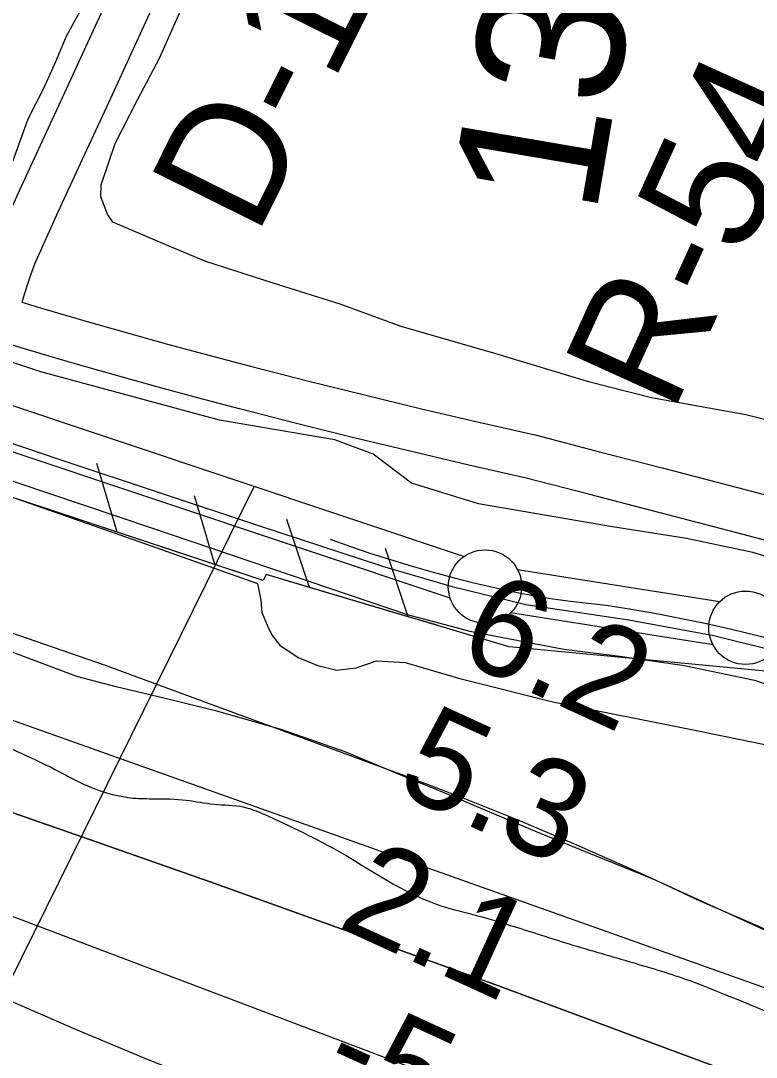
# Model space of a CAD drawing. Extents: x 3734862 to 3772949, y 391520 to 417239.
# Drawn here: x 3741720 to 3742221, y 407967 to 408673 of the extents above; entities that cross this region are included whole.
import ezdxf

# ---------------------------------------------------------------- set-up
doc = ezdxf.new("R2010")
doc.units = 0
for name, color, linetype in [('V-FLOD-BASE', 7, 'Continuous'), ('V-LEVE-TOET', 7, 'Continuous'), ('V-RIVR-EDGE', 7, 'Continuous'), ('V-RIVR-RANG', 7, 'Continuous'), ('V-RIVR-RANG-IDEN', 7, 'Continuous'), ('V-ROAD-CNTR', 7, 'Continuous'), ('V-RRAP-FSHR', 7, 'Continuous'), ('V-SITE-VEGE', 7, 'Continuous'), ('V-SURV-IDEN', 7, 'Continuous'), ('V-SURV-LINE', 7, 'Continuous'), ('V-TOPO-DPTH', 7, 'Continuous'), ('V-TOPO-MINR', 7, 'Continuous'), ('V-TOPO-WATR', 7, 'Continuous')]:
    doc.layers.add(name, color=color, linetype=linetype)

msp = doc.modelspace()

# ---------------------------------------------------------------- linework, layer by layer
at = {"layer": 'V-FLOD-BASE'}
msp.add_lwpolyline([(3741357.137, 408502.83400000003), (3741447.661, 408473.662), (3741558.435, 408435.67), (3741637.4250000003, 408410.916), (3741748.199, 408373.435), (3741882.3140000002, 408328.918), (3741966.682, 408301.315), (3742013.1040000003, 408287.751), (3742064.154, 408275.195), (3742134.474, 408264.605), (3742192.2090000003, 408254.074), (3742233.255, 408243.873), (3742303.0100000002, 408221.98600000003), (3742379.4250000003, 408196.218), (3742465.843, 408167.578), (3742525.589, 408147.021), (3742568.413, 408132.703), (3742689.193, 408092.609), (3742775.093, 408062.946), (3742799.1890000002, 408053.079), (3742852.9990000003, 408026.12700000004)], dxfattribs=at)
at = {"layer": 'V-LEVE-TOET'}
for points in [[(3742853.687, 408092.552), (3742773.204, 408127.843), (3742640.359, 408169.016), (3742476.767, 408225.74), (3742318.301, 408280.384), (3742218.792, 408310.623), (3742173.634, 408320.071), (3742123.335, 408328.00200000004), (3742031.98, 408343.821), (3741986.33, 408357.895), (3741960.222, 408377.531), (3741934.071, 408387.409), (3741855.5470000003, 408400.602), (3741733.963, 408433.507), (3741608.312, 408475.164), (3741420.097, 408539.188), (3741268.3030000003, 408592.77400000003)], [(3741157.722, 408544.851), (3741405.9390000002, 408460.52400000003), (3741600.835, 408397.49700000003), (3741810.0810000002, 408327.216), (3741983.424, 408268.395), (3742026.004, 408256.904), (3742090.153, 408244.802), (3742128.14, 408240.00800000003), (3742172.284, 408233.647), (3742220.007, 408223.67100000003), (3742324.631, 408188.788), (3742481.555, 408134.14900000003), (3742625.667, 408085.22000000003), (3742673.369, 408070.624), (3742762.594, 408038.376), (3742798.487, 408024.862), (3742869.1920000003, 407985.507)]]:
    msp.add_lwpolyline(points, dxfattribs=at)
at = {"layer": 'V-RIVR-EDGE'}
msp.add_spline([(3740900.5804832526, 408488.7607591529), (3740941.700981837, 408478.2594238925), (3740985.5366537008, 408468.65569270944), (3741012.202688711, 408464.06816566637), (3741026.2005238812, 408456.3468507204), (3741048.315927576, 408440.0144431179), (3741059.5974714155, 408430.9433678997), (3741079.4632746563, 408419.1381125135), (3741115.5910482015, 408400.96242050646), (3741134.5491848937, 408387.8029326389), (3741159.8363902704, 408374.1756358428), (3741187.834296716, 408359.637318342), (3741219.450570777, 408345.5422126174), (3741247.458539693, 408335.07330087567), (3741273.6657101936, 408327.7739547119), (3741324.259127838, 408308.2060164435), (3741367.6303449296, 408293.62968516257), (3741397.445820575, 408282.704145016), (3741437.1953158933, 408266.32813337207), (3741481.0086267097, 408247.6812782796), (3741515.791112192, 408234.0305023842), (3741546.0553898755, 408221.74737559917), (3741577.679490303, 408210.8173632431), (3741596.214540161, 408209.4150545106), (3741611.5923230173, 408211.18566551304), (3741627.866591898, 408209.7889470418), (3741654.51921028, 408199.77554565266), (3741683.8858838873, 408190.20759214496), (3741714.59896361, 408176.56687872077), (3741739.890641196, 408164.7482067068), (3741769.245016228, 408150.2065350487), (3741796.809773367, 408143.3559909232), (3741811.2776535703, 408142.86805705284), (3741832.9789148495, 408141.91007814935), (3741851.9627667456, 408139.1501827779), (3741871.853167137, 408137.29236369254), (3741889.019449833, 408130.9196909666), (3741941.855759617, 408104.11166330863), (3741978.426744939, 408082.31760368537), (3742006.4302416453, 408070.04006716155), (3742031.2820616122, 408063.1962313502), (3742056.132763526, 408055.90023934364), (3742093.6326583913, 408044.05137991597), (3742137.0083476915, 408031.2836734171), (3742175.8635930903, 408018.9793036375), (3742202.51509342, 408008.5137460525), (3742263.040294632, 407982.591023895), (3742313.1670213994, 407957.1461731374), (3742385.8803149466, 407923.0544520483), (3742430.1390736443, 407901.69354173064), (3742465.818045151, 407884.87543636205), (3742513.6962895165, 407864.40989401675), (3742632.029282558, 407810.7625332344), (3742679.00656869, 407791.6556955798), (3742732.3028610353, 407768.01164323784), (3742777.463696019, 407745.7441844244), (3742821.2848332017, 407730.2624227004), (3742862.3919151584, 407714.3352130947), (3742898.537577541, 407703.39402021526), (3742934.681003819, 407691.54851494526), (3742978.0555750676, 407678.32865225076), (3743028.200190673, 407660.11830062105), (3743075.641931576, 407645.98406306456), (3743127.6052344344, 407631.8386449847), (3743163.743070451, 407617.732358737), (3743235.1267286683, 407594.4957404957), (3743327.2916830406, 407563.97319271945), (3743354.8609123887, 407558.931273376), (3743372.940451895, 407556.1736141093), (3743388.7569743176, 407552.51723271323), (3743422.1841092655, 407539.32196717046), (3743470.5256903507, 407523.37686872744), (3743543.2837059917, 407507.37139545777), (3743582.5978159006, 407497.7788447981), (3743628.681970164, 407483.1958052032), (3743672.9563815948, 407468.16508162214), (3743714.522328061, 407454.9496911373), (3743752.478851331, 407444.9083384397), (3743782.3122158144, 407441.2172974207), (3743812.5921462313, 407435.2643573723), (3743846.038288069, 407429.75574715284), (3743877.2147045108, 407420.63547763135), (3743909.2808986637, 407405.63494146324), (3743934.1014131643, 407386.1307321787), (3743951.2453348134, 407370.7149355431), (3743984.2001886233, 407349.3819765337), (3744023.0464896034, 407333.4603571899), (3744065.9756129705, 407322.95454972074), (3744101.675827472, 407314.7274120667), (3744133.7587924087, 407306.50921883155), (3744170.3599651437, 407296.92337648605), (3744207.4121760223, 407286.884259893), (3744225.0339690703, 407281.86693770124), (3744312.23862192, 407256.7825628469), (3744386.801908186, 407239.4161487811), (3744416.179762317, 407234.36975722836), (3744442.3969952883, 407231.13981682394), (3744469.5274850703, 407231.5248898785), (3744498.9198738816, 407232.35652886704), (3744525.594853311, 407231.3862513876), (3744550.005697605, 407229.06509558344), (3744580.7321939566, 407220.850256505), (3744636.7637845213, 407206.2426197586), (3744682.3857201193, 407187.5912924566), (3744706.329873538, 407179.39322416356), (3744748.361392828, 407171.602589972), (3744781.8041805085, 407164.7375111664), (3744803.051049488, 407162.87633792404), (3744835.5772262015, 407151.03977707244), (3744852.283526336, 407141.50312903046), (3744920.944184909, 407114.20381334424), (3744972.8773003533, 407087.85017798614), (3745004.947966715, 407074.6582666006), (3745034.319112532, 407066.8989378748), (3745066.8575878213, 407060.0360951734), (3745090.817393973, 407058.1682136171), (3745113.40731491, 407050.8778118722), (3745145.9211930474, 407034.06753287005), (3745173.0181412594, 407020.8879200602), (3745183.3730116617, 407002.775957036), (3745197.806232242, 406988.2711811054), (3745221.284812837, 406974.64835651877), (3745251.1047606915, 406965.53144115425), (3745295.845862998, 406956.3776300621), (3745336.0832921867, 406954.46949862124), (3745373.6077842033, 406952.568075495), (3745407.9593564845, 406947.5093853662), (3745449.9897577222, 406939.26659497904), (3745482.9826253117, 406933.30694661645), (3745526.394092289, 406935.00823837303), (3745594.221993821, 406936.64915530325), (3745631.750958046, 406936.55635695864), (3745647.5876054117, 406941.03878708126), (3745660.719141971, 406948.6930188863), (3745673.8327896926, 406949.1127515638), (3745691.0091348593, 406946.80948459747), (3745714.498895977, 406937.7082219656), (3745744.7553472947, 406922.2600018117), (3745760.5428003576, 406906.8475593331), (3745773.1618058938, 406890.08647463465), (3745781.290554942, 406885.9969439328), (3745798.0080355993, 406880.98185784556), (3745819.7081788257, 406879.5717227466), (3745874.386654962, 406866.32390874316), (3745905.104206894, 406854.4918201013), (3745930.8379782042, 406838.6026242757), (3745969.2108799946, 406814.09115526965), (3745999.0162931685, 406799.0962093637), (3746028.82953271, 406787.2663568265), (3746069.4978750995, 406776.7661396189), (3746110.167335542, 406766.71807860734), (3746144.959883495, 406757.1367084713), (3746173.873282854, 406747.1177168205), (3746214.5427432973, 406737.0696558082), (3746271.4786462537, 406722.4597829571), (3746336.102322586, 406708.2830594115), (3746374.5031756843, 406695.07549529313), (3746423.295794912, 406678.67712260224), (3746514.1210514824, 406654.940271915), (3746563.3725352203, 406641.25371834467), (3746619.392945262, 406622.1245196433), (3746668.6388387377, 406606.1771850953), (3746708.3995145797, 406594.3227354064), (3746774.3651248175, 406574.26462716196), (3746826.3396081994, 406564.6407710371), (3746866.124881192, 406562.73375764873), (3746897.312478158, 406558.135050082), (3746931.657342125, 406550.36342278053)], degree=3, dxfattribs=at)
at = {"layer": 'V-RIVR-RANG'}
msp.add_line((3741879.0770999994, 408355.3277000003), (3741480.6760999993, 407548.31060000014), dxfattribs=at)
at = {"layer": 'V-ROAD-CNTR'}
for points in [[(3741692.6233325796, 408489.74363223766), (3741693.2772389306, 408492.045513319), (3741695.9630441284, 408500.7619267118), (3741698.840916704, 408509.41526300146), (3741702.05726126, 408518.41580500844), (3741718.5689345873, 408554.979109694), (3741735.02763571, 408590.9393727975), (3741751.641253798, 408626.75417248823), (3741802.5522428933, 408737.652365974), (3741853.1959602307, 408847.74888177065), (3741899.205737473, 408948.41802630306), (3741952.585300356, 409063.1242358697), (3742010.331281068, 409189.4127065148), (3742072.735830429, 409326.25786089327), (3742124.7849146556, 409442.0943332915), (3742189.1470783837, 409580.94240530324), (3742253.4802625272, 409720.53129551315), (3742308.771171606, 409840.09096228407), (3742388.711897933, 410014.5776341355), (3742473.8403317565, 410199.3201933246), (3742557.8918733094, 410384.89351832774), (3742657.291548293, 410602.167595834)], [(3741721.326470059, 408480.99995872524), (3741722.0447610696, 408483.528486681), (3741724.5349558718, 408491.6100732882), (3741727.2030832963, 408499.63273699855), (3741729.89873874, 408507.1761949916), (3741745.879065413, 408542.562890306), (3741762.2743642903, 408578.3846272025), (3741778.8807462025, 408614.1838275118), (3741829.811757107, 408725.1256340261), (3741880.46603977, 408835.2451182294), (3741926.448262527, 408935.85397369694), (3741979.8266996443, 409050.55776413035), (3742037.6207189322, 409176.9512934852), (3742100.066169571, 409313.88613910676), (3742152.0770853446, 409429.6376667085), (3742216.378921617, 409568.35559469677), (3742280.717737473, 409707.95670448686), (3742336.022828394, 409827.5470377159), (3742415.972102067, 410002.0523658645), (3742501.1276682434, 410186.85380667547), (3742585.196126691, 410372.4644816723), (3742684.566451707, 410589.674404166)], [(3741720.9785414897, 408481.10461789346), (3741735.9615099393, 408476.5976438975), (3741764.004915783, 408468.38012087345), (3741792.1059018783, 408460.3536876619), (3741820.2614836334, 408452.5256068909), (3741848.4705438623, 408444.8906561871), (3741876.72741377, 408437.4530646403), (3741915.4980881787, 408427.5546783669), (3741954.3370516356, 408417.90304680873), (3741993.2384627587, 408408.5048984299), (3742032.19885721, 408399.35810911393), (3742071.4887024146, 408390.403258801), (3742114.4159914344, 408379.23595177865), (3742157.126348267, 408368.1281190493), (3742199.8363931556, 408357.02136742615), (3742242.805178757, 408345.85236043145), (3742275.401147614, 408336.12797545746), (3742307.7226066, 408326.25512218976), (3742339.9798863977, 408316.1673254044), (3742372.1706110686, 408305.86400678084), (3742404.291386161, 408295.3493096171), (3742436.3423595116, 408284.6238626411), (3742468.100588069, 408273.7612237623), (3742478.935585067, 408270.34939480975)], [(3742234.7408212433, 408316.95163956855), (3742192.2876068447, 408327.9866325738), (3742149.5756517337, 408339.0938809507), (3742106.864008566, 408350.20204822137), (3742064.3772975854, 408361.254741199), (3742025.43714279, 408370.1298908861), (3741986.2875372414, 408379.32110157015), (3741947.1969483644, 408388.7649531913), (3741908.1699118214, 408398.4633216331), (3741869.19858623, 408408.41293535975), (3741840.7334561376, 408415.90534381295), (3741812.3245163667, 408423.5943931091), (3741783.9680981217, 408431.4783123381), (3741755.667084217, 408439.56187912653), (3741727.422490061, 408447.83835610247), (3741698.679473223, 408456.4844418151)], [(3741930.926, 408319.554), (3741944.819, 408314.639), (3741958.789, 408309.943), (3741972.832, 408305.466), (3741986.94, 408301.21), (3742001.117, 408297.178), (3742015.3540000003, 408293.367), (3742029.649, 408289.781), (3742044, 408286.42), (3742058.399, 408283.282)], [(3742058.399, 408283.282), (3742070.433, 408281.058), (3742082.512, 408279.096), (3742094.632, 408277.396), (3742106.787, 408275.963), (3742118.969, 408274.791), (3742136.119, 408271.994), (3742153.2260000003, 408268.95), (3742170.288, 408265.66500000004), (3742187.302, 408262.139), (3742204.2660000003, 408258.37200000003), (3742221.1720000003, 408254.365), (3742238.019, 408250.117)]]:
    msp.add_lwpolyline(points, dxfattribs=at)
at = {"layer": 'V-RRAP-FSHR'}
for p, q in [((3741786.059, 408324.37200000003), (3741772.077, 408371.159)), ((3741852.495, 408302.32300000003), (3741838.512, 408349.109)), ((3741916.958, 408286.803), (3741901.509, 408333.125)), ((3741984.055, 408266.857), (3741968.606, 408313.18))]:
    msp.add_line(p, q, dxfattribs=at)
for points in [[(3738902.293381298, 409472.05737969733), (3740332.6069263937, 408753.8471600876), (3741222.946255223, 408371.2807597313), (3742367.6717602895, 407964.03391135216)], [(3741885.294, 408291.43700000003), (3741623.779, 408378.232), (3741440.632, 408438.30700000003), (3741241.33, 408499.824), (3741053.031, 408559.014), (3740880.236, 408628.54600000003), (3740717.648, 408719.542), (3740545.6350000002, 408780.531), (3740315.4960000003, 408858.271), (3740127.6350000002, 408979.39), (3739988.6410000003, 409101.918), (3739872.917, 409177.10000000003), (3739715.1920000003, 409236.84500000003), (3739511.406, 409313.517), (3739328.592, 409381.064), (3739254.605, 409391.05700000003), (3739223.7120000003, 409392.859)], [(3741786.059, 408324.37200000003), (3741719.623, 408346.422)], [(3741852.495, 408302.32300000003), (3741786.058, 408324.373)], [(3741916.958, 408286.803), (3741887.461, 408295.571), (3741885.294, 408291.43700000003), (3741852.494, 408302.32300000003)], [(3744098.274, 407565.304), (3743827.379, 407635.72000000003), (3743592.332, 407695.86100000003), (3743255.415, 407779.58400000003), (3743049.168, 407872.952), (3742832.975, 408002.576), (3742229.916, 408229.48600000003), (3742052.933, 408246.38300000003), (3741887.461, 408295.571), (3741885.294, 408291.43700000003)], [(3741984.055, 408266.857), (3741916.957, 408286.803)], [(3742003.843, 408260.97500000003), (3741984.054, 408266.858)]]:
    msp.add_lwpolyline(points, dxfattribs=at)
at = {"layer": 'V-SITE-VEGE'}
for points in [[(3742308.894, 408380.407), (3742213.957, 408404.284), (3742149.918, 408415.827), (3742107.758, 408426.646), (3742043.127, 408446.00800000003), (3741979.43, 408464.428), (3741937.917, 408479.62200000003), (3741891.399, 408494.21400000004), (3741846.443, 408508.798), (3741820.2290000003, 408519.54600000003), (3741783.097, 408535.657), (3741779.369, 408540.988), (3741774.731, 408552.891), (3741775.083, 408561.018), (3741784.588, 408589.114), (3741800.044, 408619.371), (3741814.863, 408647.13), (3741836.029, 408695.496)], [(3741762.031, 408681.911), (3741751.156, 408661.953), (3741744.043, 408644.63300000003), (3741735.833, 408626.693), (3741725.112, 408605.637), (3741714.821, 408577.389), (3741707.255, 408563.668), (3741696.313, 408563.873), (3741687.568, 408565.788), (3741660.573, 408576.853), (3741649.809, 408581.434), (3741637.636, 408586.177), (3741615.943, 408594.093), (3741608.142, 408597.566), (3741598.779, 408601.204), (3741565.1920000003, 408605.887), (3741538.93, 408606.47500000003), (3741521.4420000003, 408610.618), (3741486.944, 408621.716), (3741465.096, 408629.632), (3741443.25, 408638.328), (3741420.7830000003, 408648.277), (3741386.6, 408659.842), (3741359.126, 408668.251)], [(3741267.1750000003, 408500.05100000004), (3741435.865, 408441.818), (3741624.3340000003, 408379.848), (3741801.34, 408317.754), (3741881.608, 408289.439), (3741883.8170000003, 408278.14400000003), (3741884.471, 408269.802), (3741888.4250000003, 408260.582), (3741891.52, 408253.969), (3741896.701, 408247.522), (3741909.166, 408239.132), (3741922.684, 408233.514), (3741935.519, 408230.503), (3741948.723, 408232.011), (3741962.463, 408236.80700000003), (3741982.078, 408235.679), (3742018.4960000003, 408224.922), (3742082.668, 408208.831), (3742180.341, 408189.291), (3742291.193, 408166.567), (3742428.9790000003, 408108.297), (3742590.3570000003, 408046.101), (3742710.724, 408015.172), (3742817.656, 407969.545)], [(3742259.89, 408039.427), (3742219.3370000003, 408057.496), (3742182.944, 408073.114), (3742153.037, 408087.174), (3742071.992, 408120.14900000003), (3742008.735, 408147), (3741976.494, 408159.995), (3741941.313, 408174.912), (3741897.6210000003, 408190.043), (3741853.7490000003, 408202.569), (3741818.537, 408211.23600000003), (3741785.235, 408219.026), (3741758.525, 408226.092), (3741701.494, 408247.532), (3741651.052, 408267.033), (3741611.884, 408283.012), (3741572.878, 408297.60000000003), (3741526.239, 408312.917), (3741454.1, 408334.945), (3741400.176, 408352.032), (3741354.915, 408365.43200000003)]]:
    msp.add_lwpolyline(points, dxfattribs=at)
at = {"layer": 'V-SURV-LINE'}
for points in [[(3740908.4490125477, 408680.0622699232), (3742022.2388270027, 408307.9302322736)], [(3742012.7490834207, 408279.4706980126), (3740898.9594024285, 408651.6026910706)], [(3742058.515962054, 408299.06509452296), (3742196.4269493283, 408277.2605802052)], [(3742191.752784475, 408247.62694555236), (3742053.842360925, 408269.4313707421)]]:
    msp.add_lwpolyline(points, dxfattribs=at)
for centre in [(3742036.447340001, 408287.36804), (3742213.82162, 408259.3235899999)]:
    msp.add_circle(centre, 25, dxfattribs=at)
at = {"layer": 'V-TOPO-DPTH'}
for points in [[(3741344.1757719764, 408256.8803595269), (3741361.763542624, 408250.8929114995), (3741379.3922432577, 408245.0237309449), (3741519.8005438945, 408199.0638355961), (3741602.4312121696, 408171.63878150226), (3741684.9068352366, 408143.76118395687), (3741767.1498904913, 408115.2047712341), (3741849.2379005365, 408086.19581505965), (3741944.277962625, 408052.16852125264), (3741978.705863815, 408039.76864273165), (3742013.1020652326, 408027.2819560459), (3742047.450716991, 408014.6650571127), (3742081.7676689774, 408001.96135001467), (3742154.060026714, 407975.0438151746), (3742224.5397753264, 407948.9264685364), (3742295.073380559, 407922.9561001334), (3742365.6877707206, 407897.20619908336), (3742436.3560175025, 407871.60327626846), (3742746.9182101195, 407759.6358470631), (3742769.2256532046, 407751.6652469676), (3742791.5628874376, 407743.77981111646), (3742813.9448083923, 407736.02212163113)], [(3742807.6368422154, 407616.30608748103), (3742777.9447145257, 407626.4862109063), (3742748.2722379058, 407636.7230311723), (3742718.629237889, 407647.0448966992), (3742689.005888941, 407657.4234590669), (3742584.292799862, 407694.278416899), (3742502.2553190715, 407722.91572695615), (3742420.121409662, 407751.27138134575), (3742337.8428573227, 407779.2045522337), (3742255.467876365, 407806.8560674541), (3742015.1876293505, 407886.8265702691), (3741986.610928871, 407896.57519909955), (3741958.136234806, 407906.6066211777), (3741929.814550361, 407917.06223312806), (3741901.594872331, 407927.8006383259), (3741856.928760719, 407945.18040704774), (3741806.66022129, 407965.3071471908), (3741756.6683046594, 407986.08164415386), (3741707.091322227, 408007.82777634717), (3741657.7909625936, 408030.22166536), (3741263.8529723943, 408213.82029983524)], [(3742807.6368422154, 407616.30608748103), (3742777.9447145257, 407626.4862109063), (3742748.2722379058, 407636.7230311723), (3742718.629237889, 407647.0448966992), (3742689.005888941, 407657.4234590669), (3742584.292799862, 407694.278416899), (3742502.2553190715, 407722.91572695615), (3742420.121409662, 407751.27138134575), (3742337.8428573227, 407779.2045522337), (3742255.467876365, 407806.8560674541), (3742015.1876293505, 407886.8265702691), (3741986.610928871, 407896.57519909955), (3741958.136234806, 407906.6066211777), (3741929.814550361, 407917.06223312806), (3741901.594872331, 407927.8006383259), (3741856.928760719, 407945.18040704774), (3741806.66022129, 407965.3071471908), (3741756.6683046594, 407986.08164415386), (3741707.091322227, 408007.82777634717), (3741657.7909625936, 408030.22166536), (3741263.8529723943, 408213.82029983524)]]:
    msp.add_lwpolyline(points, dxfattribs=at)
at = {"layer": 'V-TOPO-MINR'}
for points in [[(3742803.59199821, 407672.5649234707), (3742778.1067845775, 407681.03993041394), (3742772.8652696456, 407682.7983173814), (3742767.6300411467, 407684.5750683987), (3742762.404242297, 407686.37936549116), (3742757.1847298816, 407688.2020266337), (3741982.88, 407960.88), (3741639.5684787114, 408090.9699588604), (3741567.4514388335, 408119.09262547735), (3741495.715283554, 408148.13083503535), (3741424.550455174, 408178.54235900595), (3741353.7665113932, 408209.86942591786), (3741248.695523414, 408257.58388049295), (3741230.7895914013, 408265.8586564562), (3741212.959108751, 408274.2902911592), (3741195.241800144, 408282.9572139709), (3741177.5999408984, 408291.78099552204), (3741042.605867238, 408360.4206770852), (3740957.5210023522, 408403.6769169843), (3740872.432699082, 408446.92639126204), (3740787.3392382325, 408490.16571710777), (3740702.2423389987, 408533.39827733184), (3740440.9891087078, 408666.1055584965)], [(3742809.25, 407787.49), (3742137.5557717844, 408094.25004957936), (3742098.4485726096, 408111.5792981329), (3742059.096240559, 408128.31352971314), (3742019.376209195, 408144.15523583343), (3741979.411044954, 408159.40192498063), (3741778.0340889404, 408233.63395142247), (3741719.0995901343, 408254.0894898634), (3741659.7123465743, 408273.02557149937), (3741599.645985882, 408289.6824679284), (3741539.126880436, 408304.8199075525), (3741453.958710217, 408324.40333261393), (3741435.7359336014, 408328.80284139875), (3741417.5836769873, 408333.4650213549), (3741399.5372003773, 408338.5212080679), (3741381.56124377, 408343.8400659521), (3741363.7013661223, 408349.5387312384), (3741345.925580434, 408355.48060808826)], [(3742807.6368422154, 407616.30608748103), (3742777.9447145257, 407626.4862109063), (3742748.2722379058, 407636.7230311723), (3742718.629237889, 407647.0448966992), (3742689.005888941, 407657.4234590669), (3742584.292799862, 407694.278416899), (3742502.2553190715, 407722.91572695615), (3742420.121409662, 407751.27138134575), (3742337.8428573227, 407779.2045522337), (3742255.467876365, 407806.8560674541), (3742015.1876293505, 407886.8265702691), (3741986.610928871, 407896.57519909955), (3741958.136234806, 407906.6066211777), (3741929.814550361, 407917.06223312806), (3741901.594872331, 407927.8006383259), (3741856.928760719, 407945.18040704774), (3741806.66022129, 407965.3071471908), (3741756.6683046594, 407986.08164415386), (3741707.091322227, 408007.82777634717), (3741657.7909625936, 408030.22166536), (3741263.8529723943, 408213.82029983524)]]:
    msp.add_lwpolyline(points, dxfattribs=at)
at = {"layer": 'V-TOPO-WATR'}
msp.add_lwpolyline([(3742813.9448083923, 407736.02212163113), (3742791.5628874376, 407743.77981111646), (3742769.2256532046, 407751.6652469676), (3742746.9182101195, 407759.6358470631), (3742436.3560175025, 407871.60327626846), (3742365.6877707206, 407897.20619908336), (3742295.073380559, 407922.9561001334), (3742224.5397753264, 407948.9264685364), (3742154.060026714, 407975.0438151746), (3742081.7676689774, 408001.96135001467), (3742047.450716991, 408014.6650571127), (3742013.1020652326, 408027.2819560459), (3741978.705863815, 408039.76864273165), (3741944.277962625, 408052.16852125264), (3741849.2379005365, 408086.19581505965), (3741767.1498904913, 408115.2047712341), (3741684.9068352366, 408143.76118395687), (3741602.4312121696, 408171.63878150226), (3741519.8005438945, 408199.0638355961), (3741379.3922432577, 408245.0237309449), (3741361.763542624, 408250.8929114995), (3741344.1757719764, 408256.8803595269)], dxfattribs=at)

# ---------------------------------------------------------------- texts
at = {"layer": 'V-RIVR-RANG'}
for s, p in [('6.2', (3742015.4272727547, 408239.0805262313)), ('5.3', (3741974.028272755, 408148.0525262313)), ('2.1', (3741934.7887847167, 408056.0352059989)), ('-5', (3741922.649613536, 407951.60997618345))]:
    msp.add_text(s, height=67.00000000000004, rotation=335.3983257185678, dxfattribs=at).set_placement(p)
at = {"layer": 'V-RIVR-RANG-IDEN'}
for s, height, rotation, p in [('D-100', 83.00000000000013, 63.584325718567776, (3741880.6775922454, 408524.9578142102)), ('R-54.7', 82.99999799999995, 65.54442589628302, (3742163.8713151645, 408403.959215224))]:
    msp.add_text(s, height=height, rotation=rotation, dxfattribs=at).set_placement(p)
at = {"layer": 'V-SURV-IDEN'}
msp.add_text('1388+62.9', height=100, rotation=80.2897222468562, dxfattribs=at).set_placement((3742111.6254817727, 408538.526473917))

doc.saveas('drawing.dxf')
